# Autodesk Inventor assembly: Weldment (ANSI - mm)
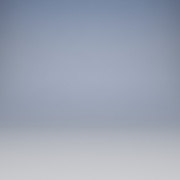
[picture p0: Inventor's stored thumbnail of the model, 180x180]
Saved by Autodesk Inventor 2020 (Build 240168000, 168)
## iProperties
Length Units: 11269
Angle Units: 11283
Time Units: 11279
Mass Units: 11290
Length Display Precision: 3
Angle Display Precision: 2
Part Number: Weldment (ANSI - mm)
Document SubType Name: Weldment
Created: 2002-06
Designer: smithga
Created: 2002-08
Designer: F.Stasiak
Weld Material: Welded Aluminum-6061
Catalog Web Link: www.expertbooks.pl
Manager: www.cadconsulting.pl
Company: Fabian Stasiak CAD Consulting
Control State: 0
Master: False
Shininess: 64.0
Angle Units: 11279
Time Units: 11290
Mass Units: 11283
Compacted: True
Density: 0.0
Volumn: 0.0
Area: 0.0
PropertySet Name: Model Information
Author: F.Stasiak
Subject: Zbiór ćwiczeń. Autodesk Inventor 2020. Kurs Professional
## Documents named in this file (1)
- M:\AUTOBUILD\M24_168_RTM\Application\App\Templates\en-US\Metric\Weldment (ANSI - mm).iam
